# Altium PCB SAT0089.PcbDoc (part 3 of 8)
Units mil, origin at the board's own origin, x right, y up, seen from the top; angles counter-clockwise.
Board outline 4075 x 2715 mil, 6 copper layers (Top Layer, InternalPlane1, MidLayer1, Internal Plane 3, InternalPlane2, Bottom Layer), stack 67.4 mil thick; 538 components, 405 nets, 1716 pads, 1236 vias.
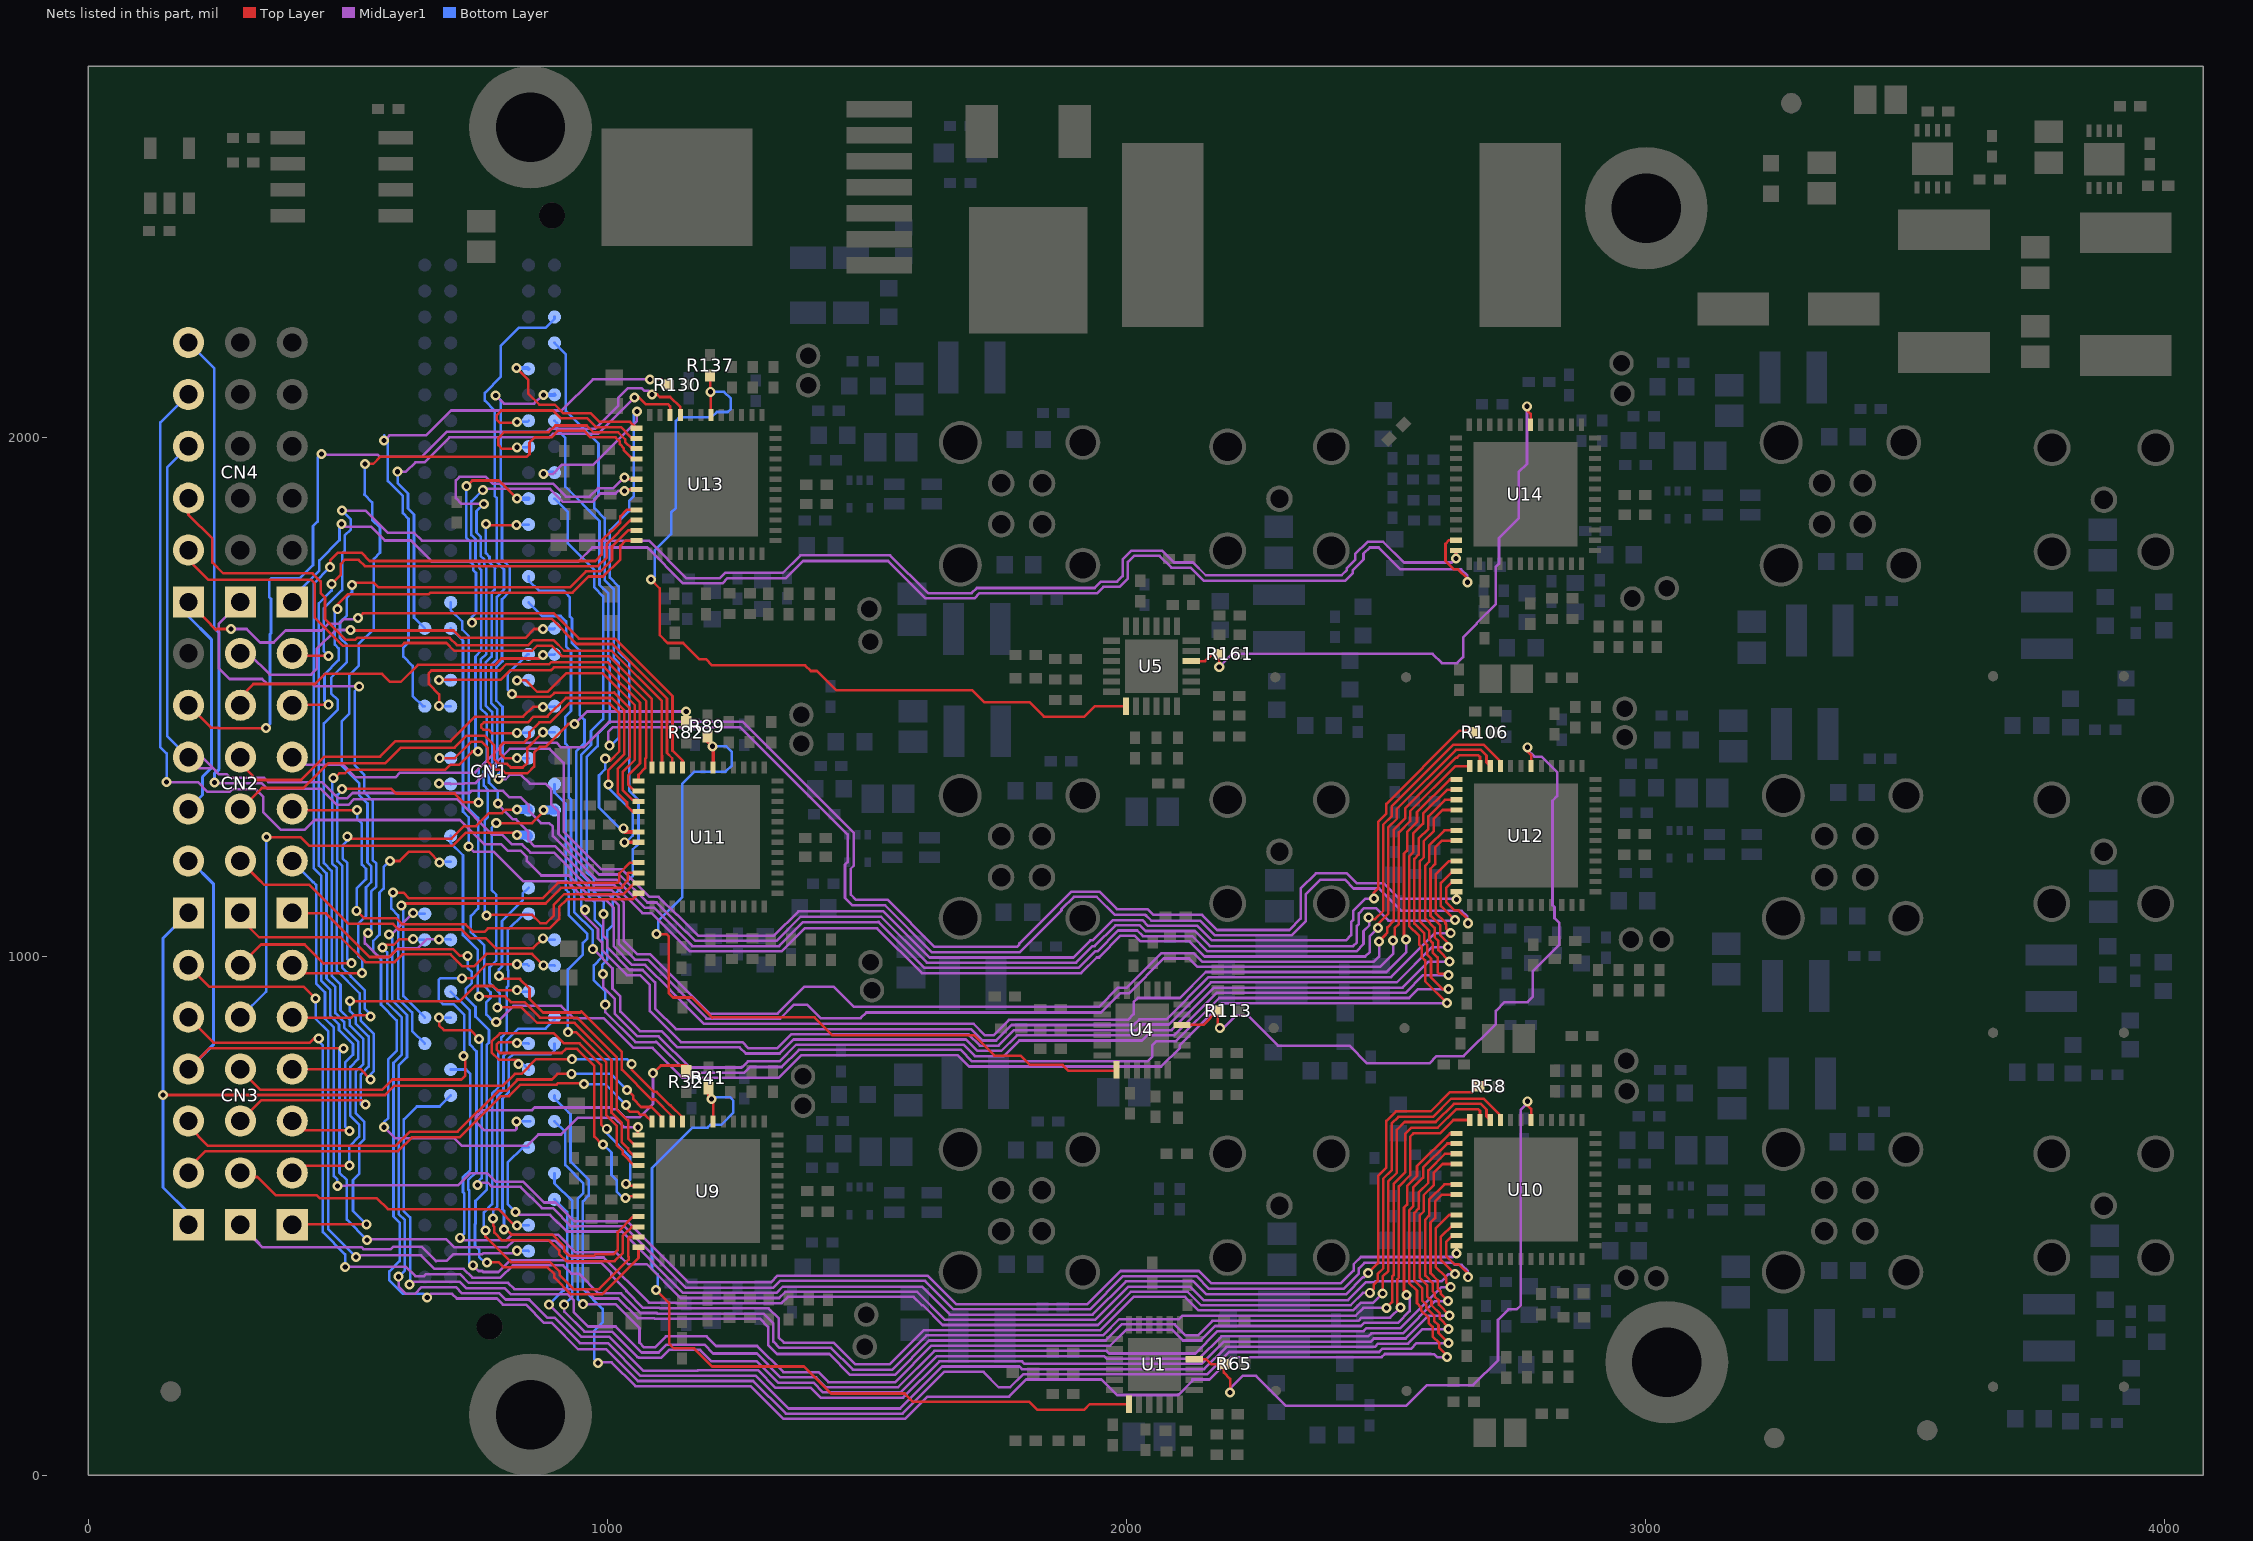
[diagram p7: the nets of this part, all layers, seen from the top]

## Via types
v1: diameter 19.29, hole 9.84, Top Layer to Bottom Layer, tented both sides, 1155 vias
v2: diameter 19.68, hole 7.87, Top Layer to Bottom Layer, tented both sides, 80 vias
v3: diameter 22, hole 10, Top Layer to Bottom Layer, tented both sides, 1 vias

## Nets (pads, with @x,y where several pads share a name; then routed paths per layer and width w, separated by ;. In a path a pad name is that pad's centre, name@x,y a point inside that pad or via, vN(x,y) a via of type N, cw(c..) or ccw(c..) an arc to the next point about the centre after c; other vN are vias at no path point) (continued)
BISTEN_CAM1: R41.1 U1.19 U9.6 | length 1636.1
  Top Layer w5: v1(1094,357) 1119,332 1119,254 1128,245 1167,245 1202,210 1379,210 1431,158 1573,158 1589,142 1813,142 1828,127 1919,127 1929.23,137.23 U1.19@2004.79,137.23 ; R41.1@1195,746 1195,731 v1(1201,725) 1203.84,722.16 U9.6@1203.84,681.86
  Bottom Layer w5: v1(1094,357) 1097,360 1097,388 1096,388 1086,398 1086,592 1164,670 1193,670 1198.5,675.5 1219.5,675.5 1243,699 1243,722 1236,729 1205,729 v1(1201,725)
BISTEN_CAM2: R65.1 U1.4 U10.6 | length 1287.3
  Top Layer w5: U1.4@2130.77,223.84 2154.16,223.84 2164,214 2187,214 2188,215 2188,198 2200,186 v1(2200,160) ; v1(2773,721) 2773,713 2779.84,706.16 U10.6@2779.84,684.86 U10.6@2780,685.02
  MidLayer1 w5: v1(2200,160) 2200,168 2224,192 2250,192 2308,134 2539,134 2579,174 2668,174 2716,222 2716,300 2736,320 2752,320 2760,328 2760,704.75 2773,717.75 v1(2773,721)
BISTEN_CAM3: R89.1 U4.19 U11.6 | length 1612.6
  Top Layer w5: v1(1095,1043) 1114,1043 1118,1039 1118,930 1127,921 1163,921 1202,882 1202.5,882.5 1399.5,882.5 1434,848 1707,848 1746,809 1796,809 1814,791 1877,791 1888,780 1979.76,780 U4.19@1981.34,781.57
  Top Layer w7: R89.1@1193,1424 1193,1415 v1(1203,1405) 1203.84,1404.16 U11.6@1203.84,1363.86
  Bottom Layer w5: v1(1095,1043) 1098,1046 1098,1068 1144,1114 1144,1332 1168,1356 1228,1356 1240,1368 1240,1394 1229,1405 v1(1203,1405)
BISTEN_CAM4: R113.1 U4.4 U12.6 | length 1417.2
  Top Layer w5: U4.4@2107.32,868.19 2148.35,868.19 2175.91,895.75 2175.91,866.09 v1(2180,862) ; v1(2773,1403) 2773,1395 2779.84,1388.16 U12.6@2779.84,1366.86 U12.6@2780,1367.02
  MidLayer1 w5: v1(2180,862) 2187,862 2212,887 2233,887 2292,828 2429.5,828 2463.5,794 2584,794 2598,808 2650,808 2712,870 2712,895 2729,912 2773,912 2783,922 2783,971 2834,1022 2834,1065 2825,1074 2825,1095 2821,1099 2821,1300 2830,1309 2830,1355 2800,1385 2786,1385 2773,1398 v1(2773,1403)
BISTEN_CAM5: R137.1 U5.19 U13.6 | length 1667.7
  Top Layer w5: v1(1084,1726) 1101,1709 1101,1619 1116,1604 1146,1604 1177,1573 1190,1573 1202,1561 1381,1561 1392,1550 1404,1550 1441,1513 1703,1513 1726,1490 1813,1490 1841,1462 1919,1462 1939.36,1482.36 U5.19@1999.06,1482.36 ; R137.1@1198,2119 1198,2089 v1(1199,2088) 1199,2044.23 U13.6@1199.84,2043.39
  Bottom Layer w5: v1(1084,1726) 1091,1733 1091,1782 1123,1814 1123,1855 1132,1864 1132,2032 1139,2039 1201,2039 1211,2049 1232,2049 1238,2055 1238,2075 1225,2088 v1(1199,2088)
BISTEN_CAM6: R161.1 U5.4 U14.6 | length 1159
  Top Layer w5: U5.4@2125.04,1568.98 2151.98,1568.98 2166,1583 2179,1583 2179,1565 2180,1564 2179,1563 v1(2179,1558) ; v1(2772,2060) 2772,2052 2778.84,2045.16 U14.6@2778.84,2024.39 ; U14.6@2778.84,2024.39 2779,2024.23 2779,2024.02 2778.84,2023.86 U14.6@2778.84,2024.39
  MidLayer1 w5: v1@2186,1558 v1(2179,1558) 2204,1583 2590,1583 2608,1565 2637,1565 2649,1577 2649,1615 2675,1641 2675,1642 2712,1679 2712,1751 2718,1757 2718,1806 2756,1844 2756,1933 2772,1949 v1(2772,2060)
CAM1_D0: CN2.1 U9.24 | length 1402.9
  Top Layer w5: CN2.1@393,1083 458,1083 542,999 579,999 587,1007 588,1007 595,1014 703,1014 716,1001 v1(731,1001) ; v1@762,410 v1(768,410) 768.5,410.5 791,410.5 800.5,401 885,401 898,388 898,381 930,349 990,349 1060.14,419.14 U9.24@1060.14,439.73
  Bottom Layer w5: v1(731,1001) 731,978 739,970 739,949 727,937 727,922 746,903 746,884 772,858 772,834 768,830 768,551 746,529 746,485 745,484 745,443 753,435 753,421 764,410 v1(768,410)
CAM1_D0_CAM1_VS: CN1.133 CN2.7 | length 685.2
  Top Layer w5: CN2.7@293,1083 293,1073 329,1037 486,1037 534,989 590,989 605,1004 698,1004 721,981 743,981 767,1005 855,1005 v1(877,983)
  Bottom Layer w5: v1(877,983) 897.43,983 CN1.133@898.27,982.17
CAM1_D1: CN1.95 U9.23 | length 1080.8
  Top Layer w5: v1(765,472) 765,460 814,411 890,411 908,393 908,386 935,359 984,359 1041,416 1041,421 1040,422 1040,457 1042.42,459.42 U9.23@1060.14,459.42
  Bottom Layer w5: v1@772,473 771,472 v1(765,472) 762,475 762,507 778,523 778,736 790,748 790,813 796,819 796,844 806,854 806,940 809,943 809,973 808,974 808,1051 839.17,1082.17 CN1.95@848.27,1082.17
CAM1_D2: CN1.131 U9.22 | length 845.6
  Top Layer w5: v1(780,495) 780,481.5 782.5,479 782.5,468 797.5,453 887.5,453 907,433.5 907,427 921,413 1014,413 1030,429 1030,462 1047.1,479.1 U9.22@1060.14,479.1
  Bottom Layer w5: v1(780,495) 780,510 788,518 788,731 800,743 800,808 806,814 806,838 829,861 881,861 898.27,878.27 CN1.131@898.27,882.17
CAM1_D3: CN1.130 U9.21 | length 790.9
  Top Layer w5: v1@798,481 v1@801,478 ; v1(801,474) v1@801,478 ; U9.21@1060.14,498.79 1049.79,498.79 1019.5,468.5 1020,468 1020,434 1012.5,426.5 977.5,426.5 974,423 926,423 917,432 917,441 894,464 815,464 v1@801,478
  Bottom Layer w5: v1(801,474) 801,510 798,513 798,726 810,738 810,803 819,812 891,812 898.27,819.27 CN1.130@898.27,832.17
CAM1_D4: CN1.90 U9.19 | length 592
  Top Layer w5: v1(826,833) 824,835 791,835 787,831 787,820 793,814 912,814 920,822 942,822 975,789 975,653 990,638 v1(992,638) ; v1(1035,535) 1038.16,538.16 U9.19@1060.14,538.16
  Bottom Layer w5: v1(826,833) 847.43,833 CN1.90@848.27,832.17 ; v1(992,638) 1008,622 1008,579 1018,569 1018,547 1030,535 v1(1035,535)
CAM1_D5: CN1.89 U9.18 | length 636.6
  Top Layer w5: v1(829,793) 829,801 791,801 777,815 777,836 793,852 897,852 916.5,832.5 946.5,832.5 988,791 988,676 996,668 v1(999,668) ; v1(1036,562) 1040.16,557.84 U9.18@1060.14,557.84
  Bottom Layer w5: v1(829,793) 837.43,793 CN1.89@848.27,782.17 ; v1(999,668) 999,659 1044,614 1044,570 v1(1036,562)
CAM1_D6: CN1.140 U9.16 | length 846.9
  Top Layer w5: v1(924,854) 940,854 998,796 998,694 1018,674 1018,637 1030,625 1030,619 1051.79,597.21 U9.16@1060.14,597.21
  Bottom Layer w5: CN1.140@898.27,1332.17 898.27,1315.73 920,1294 920,1129 925.5,1123.5 925.5,1079.5 961,1044 961,1034 953,1026 953,1004 924,975 v1(924,854)
CAM1_D7: CN1.139 U9.15 | length 978.3
  Top Layer w5: v1(786,1257) 855,1257 879,1281 878,1281 v1(877,1282) ; v1(788,902) 835,902 865,872 937,872 1008,801 1008,699 1028,679 1028,642 1040,630 1040,627 1050.1,616.9 U9.15@1060.14,616.9
  Bottom Layer w5: v1(786,1257) 777,1248 777,1128 786,1119 786,992 773,979 773,949 793,929 793,907 v1(788,902)
  Bottom Layer w17.72: v1(877,1282) 898.1,1282 CN1.139@898.27,1282.17
CAM1_D8: CN1.58 U9.14 | length 840.9
  Top Layer w5: v1(753,923) 769,923 770,922 771,923 803,923 814,912 840,912 870,882 942,882 1018,806 1018,705 1039,684 1040,684 1040,649 1052.42,636.58 U9.14@1060.14,636.58
  Bottom Layer w5: CN1.58@698.27,1232.17 698.27,1218.73 722,1195 722,1041 750,1013 750,926 v1(753,923) v1@755,921
CAM1_D9: CN1.57 U9.13 | length 1246.1
  Top Layer w5: v1(581,1184) 600,1184 618,1202 656,1202 v1(677,1181) ; v1(1059,671) 1059,657.41 U9.13@1060.14,656.27
  MidLayer1 w5: v1(570,671) 591,650 705,650 720,635 845,635 867,657 911,657 943,689 1014,689 1032,671 v1(1059,671)
  Bottom Layer w5: v1@578,670 577,671 v1(570,671) 570,681 578,689 578,802 594,818 594,877 564,907 564,995 549,1010 549,1030 561,1042 561,1123 569,1131 569,1172 v1(581,1184) ; v1(677,1181) 678.17,1182.17 CN1.57@698.27,1182.17
CAM1_D10: CN3.14 U9.12 | length 1010.5
  Top Layer w5: CN3.14@193,582 CN3.14@193,583 193,592 226,625 597,625 623.5,651.5 715.5,651.5 795,731 811,731 833,753 902,753 905,756 953,756 v1(955,754) ; v1(1036,714) 1032,714 1032,712 1043,701 1058,701 1064,695 1072.59,695 U9.12@1085.73,681.86
  Bottom Layer w5: v1(955,754) 996,754 v1(1036,714)
CAM1_D11: CN3.15 U9.11 | length 1043.1
  Top Layer w5: CN3.15@193,683 193,673 231,635 592,635 619.5,662.5 711.5,662.5 790,741 806,741 826,761 826,763 893,763 904,774 v1(931,774) ; v1(1038,743) 1050,731 1050,725 1065,710 1085,710 1105.42,689.58 U9.11@1105.42,681.86
  Bottom Layer w5: v1(931,774) 1007,774 v1(1038,743)
CAM1_HS: CN1.96 U9.10 | length 687.8
  Top Layer w5: U9.10@1125.1,681.86 1125.1,691.9 1092.5,724.5 1085.5,724.5 1028,782 1028,816 950,894 948,892 876,892 850,918 850,938 832,956 832,957 796,957 v1@793,960 ; v1@793,960 v1(791,962) 791,960 v1@793,960
  Bottom Layer w5: v1(791,962) 791,975 797,981 797,1068 837,1108 837,1120.9 CN1.96@848.27,1132.17
CAM1_PCLK: CN1.87 R32.1 | length 644.1
  Top Layer w5: v1(1088,775) 1103,790 1152,790 R32.1@1152,779
  MidLayer1 w5: v1(825,682) 825,668 822,665 763,665 747,681 747,691 760,704 855,704 860,709 1006,709 1009,706 1018,706 1034,690 1062,690 1088,716 v1(1088,775)
  Bottom Layer w5: v1(825,682) 825.17,682.17 CN1.87@848.27,682.17 CN1.87@851.83,682.17
CAM1_VS: CN2.13 CN3.13 U9.9 | length 1737.1
  Top Layer w5: v1(144,733) 572,733 590,751 799,751 822,774 835,774 863,802 v1(932,802) ; CN3.13@192,483 CN3.13@193,483 CN3.13@193,482 ; v1(1047,793) 1047,782 1090,739 1095,739 1121,713 1122,713 1144.79,690.21 U9.9@1144.79,681.86
  Bottom Layer w5: v1(932,802) 1038,802 v1(1047,793)
  Bottom Layer w6: CN3.13@193,482 CN3.13@193,483 193,506 144,555 v1(144,733) 144,1035 CN2.13@192,1083 ; CN2.13@192,1083 CN2.13@193,1084 193,1083 CN2.13@192,1083
CAM2_D0: CN2.2 U10.24 | length 3084
  Top Layer w5: v1(2636,428) 2636.14,428.14 U10.24@2636.14,442.73
  MidLayer1 w5: v1(480,558) 497,558 498,559 712,559 735,582 769,582 785,566 838,566 878,526 900,526 936,490 1038,490 1156,372 1315,372 1328,385 1617,385 1672,330 1925,330 1989,394 2140,394 2164,370 2413,370 2438,395 2438,407 2452,421 2629,421 v1(2636,428)
  Bottom Layer w5: v1(480,558) 480,570 473,577 473,863 456,880 456,931 439,948 439,1138 434,1143 ; 434,1143 433,1143 393,1183 CN2.2@393,1184 434,1143
CAM2_D0_CAM2_VS: CN1.134 CN2.8 | length 738.9
  Top Layer w5: v1(876,1035) 857,1016 785,1016 766,1035 736,1035 719,1052 598,1052 587,1063 501,1063 426,1138 339,1138 331.5,1145.5 ; 331.5,1145.5 330.5,1145.5 293,1183 CN2.8@293,1184 331.5,1145.5
  Bottom Layer w5: v1(876,1035) 878.83,1032.17 CN1.134@898.27,1032.17
CAM2_D1: CN1.51 U10.23 | length 2630.6
  Top Layer w5: v1(676,882) 676,867 685,858 736,858 v1(753,841) ; U10.23@2636.14,462.42 2628.42,462.42 2616,450 2616,423 2632,407 2640,407 2658,389 v1(2658,382)
  MidLayer1 w5: v1(750,560) 754,564 770,564 778,556 833,556 874,515 895,515 930,480 1033,480 1151,362 1320,362 1333,375 1612,375 1667,320 1930,320 1994,384 2135,384 2159.5,359.5 2418.5,359.5 2448,389 2448,399 2458.5,409.5 2629.5,409.5 2633,406 2646,406 2658,394 v1(2658,382)
  Bottom Layer w5: v1(676,882) 698.1,882 CN1.51@698.27,882.17 ; v1(750,560) 750,566 751,566 758,573 758,836 v1(753,841)
CAM2_D2: CN1.49 U10.22 | length 2549
  Top Layer w5: v1(2633,388) 2606,415 2606,460 2628.1,482.1 U10.22@2636.14,482.1
  MidLayer1 w5: v1(716,458) 721,453 805,453 816,464 905,464 939,430 1017,430 1040,407 1076,407 1141,342 1331,342 1343,354 1597,354 1651,300 1940,300 2004,364 2123,364 2149,338 2427,338 2461,372 2478,372 2480,374 2607,374 2621,388 v1(2633,388)
  Bottom Layer w5: CN1.49@698.27,782.17 727.83,782.17 736,774 736,589 722,575 722,546 724,544 724,466 v1(716,458)
CAM2_D3: CN1.48 U10.21 | length 2810.8
  Top Layer w5: v1(2625,363) 2616,372 2616,380 2615,381 2615,383 2596,402 2596,476 2621.79,501.79 U10.21@2636.14,501.79
  MidLayer1 w5: v1(619,368) 624,373 716,373 728,361 802,361 814,349 924,349 935,338 935,315 963,287 1016,287 1066,237 1099,237 1114,252 1187,252 1204,235 1288,235 1334,189 1402,189 1421,170 1560,170 1630,240 1962,240 1967,235 2133,235 2176,278 2457,278 2463,284 2528,284 2607,363 v1(2625,363)
  Bottom Layer w5: v1(619,368) 620,369 620,497 608,509 608,686 633,711 677.1,711 CN1.48@698.27,732.17
CAM2_D4: CN1.125 U10.19 | length 2400.3
  Top Layer w5: v1(2620,336) 2605.5,350.5 2605.5,354.5 2600,360 2600,376 2586,390 2586,487 2595,496 2595,528 2608.16,541.16 U10.19@2636.14,541.16
  MidLayer1 w5: v1(917,329) 917,316 956,277 1009,277 1058,228 1060,228 1061,227 1104,227 1119,242 1179,242 1201,220 1288,220 1329,179 1397,179 1416,160 1565,160 1635,230 1957,230 1962,225 2140,225 2183,268 2466,268 2472,274 2533,274 2595,336 v1(2620,336)
  Bottom Layer w5: CN1.125@898.27,582.17 898.27,562.73 932.5,528.5 932.5,344.5 v1(917,329)
CAM2_D5: CN1.124 U10.18 | length 2418.5
  Top Layer w5: v1(2623,308) 2602,329 2602,337 2594,345 2594,351 2590,355 2590,371 2576,385 2576,493 2583.5,500.5 2583.5,531.5 2612.84,560.84 U10.18@2636.14,560.84
  MidLayer1 w5: v1(888,329) 950,267 1004,267 1069,202 1174,202 1175,203 1290,203 1324,169 1392,169 1411,150 1570,150 1640,220 1799,220 1804,215 2145,215 2188,258 2471,258 2477,264 2538,264 2582,308 v1(2623,308)
  Bottom Layer w5: v1(888,329) 915,356 916,356 922.5,362.5 922.5,507.93 CN1.124@898.27,532.17
CAM2_D6: CN1.15 U10.16 | length 3382.4
  Top Layer w5: v1(2621,282) 2621,285 2604,302 2604,312 2588,328 2588,336 2580,344 2580,366 2565,381 2565,501 2573,509 2573,540 2592,559 2592,583 2609.21,600.21 U10.16@2636.14,600.21
  MidLayer1 w5: v1(579,1042) 584,1042 v1(626,1084) ; v1(598,383) 598,364 612,350 629,350 642,363 708,363 720,351 792,351 804,339 850,339 850,338 884,304 898,304 947,255 1001,255 1064,192 1286,192 1349,129 1564,129 1645,210 1794,210 1799,205 2150,205 2193,248 2479,248 2485,254 2543,254 2571,282 v1(2621,282)
  Bottom Layer w5: v1(579,1042) 586,1035 586,915 614,887 614,806 598,790 598,504 610,492 610,395 v1(598,383) ; v1(626,1084) 627.83,1082.17 CN1.15@648.27,1082.17
CAM2_D7: CN1.14 U10.15 | length 3439.2
  Top Layer w5: v1(567,1017) 572.5,1022.5 588.5,1022.5 599,1033 625,1033 v1(626,1034) ; v1(2621,255) 2601.5,274.5 2601.5,289.5 2593,298 2593,308 2578,323 2578,329 2570,337 2570,361 2555,376 2555,506 2563,514 2563,545 2582,564 2582,588 2613.9,619.9 U10.15@2636.14,619.9
  MidLayer1 w5: v1(653,343) 660,350 701,350 710,341 787,341 799,329 843,329 878,294 893,294 944,243 998,243 1059,182 1281,182 1344,119 1569,119 1650,200 1725,200 1725,199 1754,170 1776,170 1801,195 2155,195 2198,238 2487,238 2493,244 2548,244 2559,255 v1(2621,255)
  Bottom Layer w5: v1(567,1017) 576,1008 576,910 604,882 604,811 588,795 588,499 600,487 600,413 580,393 580,376 606,350 646,350 v1(653,343) ; v1(626,1034) 627.83,1032.17 CN1.14@648.27,1032.17
CAM2_D8: CN1.128 U10.14 | length 2824.9
  Top Layer w5: v1(2618,228) 2618,231 2603,246 2603,255 2590,268 2590,286 2583,293 2583,303 2568,318 2568,324 2560,332 2560,356 2545,371 2545,511 2553,519 2553,554 2552.5,554.5 2572,574 2572,593 2618.58,639.58 U10.14@2636.14,639.58
  MidLayer1 w5: v1(982,217) 983,218 1008,218 1054,172 1276,172 1339,109 1574,109 1617,152 1774,152 1807,185 1952,185 1982,155 2099,155 2100,156 2101,156 2127,182 2127,185 2160,185 2203,228 2492,228 2498,234 2587,234 2587.5,233.5 2593.5,233.5 2599,228 v1(2618,228)
  Bottom Layer w5: CN1.128@898.27,732.17 898.27,726.73 929,696 929,605 964,570 964,539 953,528 953,359 991,321 991,295 975,279 975,224 v1(982,217)
CAM2_D9: CN1.127 U10.13 | length 2552
  Top Layer w5: v1(2540,348) 2540,356 2535,356 2535,516 2541,522 2541,558 2560,577 2560,596 2623.27,659.27 U10.13@2636.14,659.27
  MidLayer1 w5: v1@948,332 950,330 v1(953,330) 1016,330 1062,284 1062,256 1071,247 1092,247 1113,268 1191,268 1209.5,249.5 1288.5,249.5 1339,199 1407,199 1426,180 1555,180 1625,250 1969,250 2000,281 2088,281 2109,260 2143,260 2171,288 2452,288 2458,294 2523,294 2546,317 2546,342 v1(2540,348)
  Bottom Layer w5: CN1.127@898.27,682.17 919,661.43 919,598 954,563 954,544 943,533 943,340 v1(953,330)
CAM2_D10: CN3.17 U10.12 | length 3420.9
  Top Layer w5: CN3.17@193,883 193,882 241,834 427,834 435,842 v1(444,842) ; v1(2528,324) 2522,330 2522,378 2525,381 2525,557 2547,579 2547,653 2553,659 2604.14,659 2630,684.86 U10.12@2661.73,684.86
  MidLayer1 w5: v1(495,402) 612,402 630,384 647,384 651,388 716,388 733,371 809,371 821,359 957,359 975,341 1021,341 1059,303 1090,303 1091,302 1294,302 1310,286 1310,251 1327,234 1428,234 1468,194 1554,194 1620,260 1960,260 1991,291 2094,291 2094,290 2114,270 2138,270 2166,298 2447,298 2453,304 2508,304 v1(2528,324)
  Bottom Layer w5: v1(444,842) 444,836 452,828 452,469 495,426 v1(495,402)
CAM2_D11: CN3.18 U10.11 | length 3503.4
  Top Layer w5: CN3.18@193,983 193,982 233,942 415,942 v1(438,919) ; v1(2501,323) 2512,334 2512,383 2515,386 2515,562 2537,584 2537,658 2549,670 2600,670 2636,706 2678,706 2681.42,702.58 U10.11@2681.42,684.86
  MidLayer1 w5: v1(516,421) 519,424 641,424 667,398 723,398 740,381 794,381 818,405 915,405 931,389 945,389 983,351 1027,351 1027,350 1064,313 1095,313 1096,312 1301,312 1320,293 1320,258 1332,246 1431,246 1473,204 1549,204 1615,270 1955,270 1986,301 2101,301 2108,308 2442,308 2457,323 v1(2501,323)
  Bottom Layer w5: v1(438,919) 438,880 462,856 462,475 v1(516,421)
CAM2_HS: CN1.52 U10.10 | length 3066.3
  Top Layer w5: v1(2494,351) 2494,383 2505,394 2505,567 2521,583 2521,666 2536,681 2596,681 2631,716 2683,716 2694,705 2694,691.96 U10.10@2701.1,684.86
  MidLayer1 w5: v1(741,405) 752,394 759,394 761,392 790,392 813,415 920,415 925,410 988,410 1008,390 1008,385 1037,356 1037,355 1069,323 1100,323 1101,322 1311,322 1330,303 1330,266 1340,256 1436,256 1478,214 1544,214 1610,280 1950,280 2014,344 2113,344 2139,318 2437,318 2452,333 2476,333 v1(2494,351)
  Bottom Layer w5: CN1.52@698.27,932.17 735,895.43 735,830 748,817 748,585 732,569 732,551 734,549 734,409 741,402 v1(741,405)
CAM2_PCLK: CN1.86 R58.1 | length 2454.6
  Top Layer w5: v1(2466,390) 2485,409 2485,577 2501,593 2501,683 2519.5,701.5 2586.5,701.5 2623.5,738.5 2666.5,738.5 R58.1@2678,750
  MidLayer1 w5: v1(823,508) 829,502 890,502 922,470 1028,470 1146,352 1326,352 1338,364 1606,364 1660,310 1935,310 1999,374 2129,374 2154,349 2423,349 2456,382 2458,382 v1(2466,390)
  Bottom Layer w5: v1(823,508) 808,523 808,603 837.17,632.17 CN1.86@848.27,632.17
CAM2_VS: CN2.14 CN3.16 U10.9 | length 3871
  Top Layer w5: 226,815 193,782 CN3.16@193,783 233,823 v1(492,823) ; v1(2469,352) 2477,360 2477,368 2484,375 2484,388 2495,399 2495,572 2511,588 2511,678 2524,691 2591,691 2626,726 2688,726 2720.79,693.21 U10.9@2720.79,684.86
  MidLayer1 w5: v1(537,454) 538,455 690,455 705,440 807,440 819,452 900,452 932,420 993,420 1080,333 1132,333 1133,332 1336,332 1348,344 1590,344 1606,328 1608,328 1646,290 1945,290 2009,354 2118,354 2144,328 2432,328 2456,352 v1(2469,352)
  Bottom Layer w5: v1(492,823) 487,823 486,824 484,822 484,583 498,569 498,493 v1(537,454)
  Bottom Layer w6: CN2.14@193,1183 198,1183 241,1140 241,830 CN3.16@194,783 ; CN3.16@194,783 CN3.16@193,783 193,782 CN3.16@194,783
CAM3_D0: CN2.3 U11.24 | length 937.6
  Top Layer w5: CN2.3@393,1283 394,1282 v1(518,1282) ; v1(517,1088) 531,1074 593,1074 605,1062 727,1062 741,1048 764,1048 770,1054 889,1054 907,1072 907,1095 922,1110 1048.41,1110 U11.24@1060.14,1121.73
  Bottom Layer w5: v1(517,1088) 517,1131 535,1149 535,1169 527,1177 527,1256 518,1265 v1(518,1282)
CAM3_D0_CAM3_VS: CN1.142 CN2.9 | length 750.4
  Top Layer w5: CN2.9@293,1283 334.5,1324.5 414.5,1324.5 462,1372 572,1372 602.5,1402.5 705.5,1402.5 728,1425 764,1425 782,1407 782,1380 791,1371 807,1371 814,1364 837,1364 846,1373 846,1402 v1(876,1432)
  Bottom Layer w5: v1(876,1432) 898.1,1432 CN1.142@898.27,1432.17
CAM3_D1: CN1.110 U11.23 | length 1240.7
  Top Layer w5: v1(766,1833) 765,1833 763,1831 v1(825,1831) ; v1@767,1072 v1(767,1079) 768,1080 855,1080 871,1064 882,1064 897,1079 897,1100 917,1120 1031,1120 1052.42,1141.42 U11.23@1060.14,1141.42
  Bottom Layer w5: v1(766,1833) 766,1777 773,1770 773,1759 784,1748 783,1747 783,1707 777,1701 777,1578 766,1567 766,1483 778,1471 778,1373 762,1357 762,1329 770,1321 770,1269 764,1263 764,1073 767,1076 v1(767,1079) ; v1(825,1831) 826.17,1832.17 CN1.110@848.27,1832.17
CAM3_D2: CN1.11 U11.22 | length 727.8
  Top Layer w5: v1(603,1098) 607,1102 881,1102 911,1132 1028,1132 1030,1134 1030,1137 1039,1146 1039,1160 1040.1,1161.1 U11.22@1060.14,1161.1
  Bottom Layer w5: v1(603,1098) 607,1094 607,923.43 CN1.11@648.27,882.17
CAM3_D3: CN1.10 U11.21 | length 845.7
  Top Layer w5: v1(587,1123) 607,1123 618,1112 875,1112 905,1142 1020,1142 1023,1145 1023,1160 1043.79,1180.79 U11.21@1060.14,1180.79
  Bottom Layer w5: v1(587,1123) 587,1126 584,1129 584,1092 597,1079 597,919 624,892 624,856.43 CN1.10@648.27,832.17
CAM3_D4: CN1.102 U11.19 | length 731.7
  Top Layer w5: v1(826,1431) 825,1430 778,1430 771,1437 761,1437 757,1441 757,1446 762,1451 847,1451 858,1462 885,1462 885,1463 920,1498 1009,1498 1033,1474 1033,1390 1002,1359 v1(1002,1331)
  Top Layer w7: v1(1033,1220) 1033.84,1220 1034,1220.16 U11.19@1060.14,1220.16
  Bottom Layer w5: v1(826,1431) 847.1,1431 CN1.102@848.27,1432.17 ; v1(1002,1331) 1002,1325 1049,1278 1049,1233 1036,1220 v1(1033,1220)
CAM3_D5: CN1.101 U11.18 | length 660.5
  Top Layer w5: v1(826,1382) 802,1382 794,1390 794,1406 800,1412 839,1412 850,1423 850,1432 869,1451 890,1451 926.5,1487.5 1004.5,1487.5 1023,1469 1023,1395 1005,1377 1001,1381 v1(996,1381) v1@992,1381
  Top Layer w7: v1(1031,1247) 1031,1242.84 1034,1239.84 U11.18@1060.14,1239.84
  Bottom Layer w5: v1(826,1382) 848.1,1382 CN1.101@848.27,1382.17 ; v1(996,1381) 996,1361 984,1349 984,1287 1024,1247 v1(1031,1247)
CAM3_D6: CN1.105 U11.16 | length 575.6
  Top Layer w5: v1(816,1506) 822,1500 890,1500 898,1508 1012,1508 1013,1509 1043,1479 1043,1384 1020,1361 1020,1315 1038,1297 1038,1290 1048.79,1279.21 U11.16@1060.14,1279.21
  Bottom Layer w5: v1(816,1506) 808,1514 808,1544 846.17,1582.17 CN1.105@848.27,1582.17
CAM3_D7: CN1.104 U11.15 | length 511.5
  Top Layer w5: v1(826,1532) 843,1532 865,1510 885,1510 921,1546 991,1546 1053,1484 1053,1379 1030,1356 1030,1320 1048,1302 1057.04,1302 U11.15@1060.14,1298.9
  Bottom Layer w5: v1(826,1532) 848.1,1532 CN1.104@848.27,1532.17
CAM3_D8: CN1.64 U11.14 | length 640.8
  Top Layer w5: v1(676,1533) 794.5,1533 813,1551.5 892,1551.5 892,1552 897,1557 995,1557 1063,1489 1063,1372 1040,1349 1040,1331 1052.42,1318.58 U11.14@1060.14,1318.58
  Bottom Layer w5: v1(676,1533) 676.83,1532.17 CN1.64@698.27,1532.17
CAM3_D9: CN1.63 U11.13 | length 712.5
  Top Layer w5: v1(676,1483) 676,1505 656,1525 656,1546 661,1551 793,1551 805,1563 888,1563 892,1567 1000,1567 1075,1492 1075,1383 1073,1381 1073,1362.86 1060.14,1350 U11.13@1060.14,1338.27
  Bottom Layer w5: v1(676,1483) 676.83,1482.17 CN1.63@698.27,1482.17
CAM3_D10: CN4.14 U11.12 | length 1206.1
  Top Layer w5: CN4.14@193,1783 193,1764 231,1726 429,1726 436.5,1718.5 436.5,1652.5 490,1599 604,1599 609,1604 690,1604 705,1589 855,1589 865,1599 892,1599 912.5,1578.5 1003.5,1578.5 1085.73,1496.27 U11.12@1085.73,1363.86
CAM3_D11: CN4.15 U11.11 | length 1295.9
  Top Layer w5: CN4.15@193,1883 193,1851 239,1805 239,1759 260,1738 432,1738 447.5,1722.5 447.5,1700.5 456,1692 456,1650.5 496.5,1610 514,1610 518,1614 696,1614 710,1600 848,1600 857,1609 897,1609 917,1589 1008,1589 1105,1492 1105,1387 1105.42,1386.58 U11.11@1105.42,1363.86
CAM3_HS: CN1.111 U11.10 | length 993.4
  Top Layer w5: v1(729,1906) 740,1917 791,1917 v1(826,1882) ; v1(739,1643) 747,1651 892,1651 941,1602 1010,1602 1115,1497 1115,1392 1125.1,1381.9 U11.10@1125.1,1363.86
  Bottom Layer w5: v1(729,1906) 728,1905 728,1807 736,1799 736,1760 742,1754 742,1744 747,1739 747,1662 739,1654 v1(739,1643)
  Bottom Layer w8: v1(826,1882) 848.1,1882 CN1.111@848.27,1882.17
CAM3_PCLK: CN1.61 R82.1 | length 645.2
  Top Layer w5: v1(677,1382) 707,1382 707,1383 738,1414 758,1414 770,1402 770,1375 785,1360 797,1360 804,1353 846,1353 859,1366 859,1393 870,1404 881,1404 925,1448 v1(937,1448) ; v1@1146,1472 v1(1152,1472) 1152,1452 R82.1@1150,1454
  MidLayer1 w5: v1(937,1448) 961,1472 v1(1152,1472)
  Bottom Layer w5: v1(677,1382) 698.1,1382 CN1.61@698.27,1382.17
CAM3_VS: CN2.15 CN4.13 U11.9 | length 1643.4
  Top Layer w5: CN4.13@193,1683 236,1640 236,1639 246,1629 248,1631 v1(275,1631) ; v1(520,1652) 529,1661 897,1661 945.5,1612.5 1014.5,1612.5 1125.5,1501.5 1125.5,1396.5 1144.79,1377.21 U11.9@1144.79,1363.86
  MidLayer1 w5: v1(275,1631) 305,1631 331,1605 357,1605 380,1628 449,1628 462,1641 483.5,1641 492,1649.5 v1@517.5,1649.5 ; v1@517.5,1649.5 v1(520,1652) 520,1649.5 v1@517.5,1649.5
  Bottom Layer w6: CN2.15@193,1283 CN2.15@193,1284 220,1311 220,1346 237,1363 237,1611 193,1655 CN4.13@193,1683
CAM4_D0: CN2.4 U12.24 | length 2762.3
  Top Layer w5: v1(2636,1110) 2636.14,1110.14 U12.24@2636.14,1124.73
  MidLayer1 w5: CN2.4@393,1383 406.5,1369.5 490.5,1369.5 515,1345 592,1345 601,1354 745,1354 803,1412 902,1412 911,1403 954,1403 1003,1452 1261,1452 1475,1238 1475,1175 1469,1169 1469,1119 1478.5,1109.5 1539.5,1109.5 1630.5,1018.5 1789.5,1018.5 1794,1023 1794,1025 1894,1125 1948,1125 1982,1091 2041,1091 2052,1080 2146,1080 2175,1051 2314,1051 2336,1073 2336,1131 2365,1160 2425,1160 2444,1141 2496,1141 2526,1111 v1@2633,1111 ; v1@2633,1111 2634,1110 v1(2636,1110) 2635,1111 v1@2633,1111
CAM4_D0_CAM4_VS: CN1.143 CN2.10 | length 688.4
  Top Layer w5: CN2.10@293,1383 293,1372 325,1340 410,1340 455,1385 562,1385 592,1415 698,1415 745,1462 838,1462 857,1481 v1(876,1481)
  Bottom Layer w5: v1(876,1481) 897.1,1481 CN1.143@898.27,1482.17
CAM4_D1: CN1.157 U12.23 | length 3097.4
  Top Layer w5: U12.23@2636.14,1144.42 2628.42,1144.42 2616,1132 2616,1105 2632,1089 2640,1089 2658,1071 v1(2658,1064)
  MidLayer1 w5: v1@1005,1406 v1(1004.5,1406) 1002,1408.5 1002,1433 1011,1442 1256,1442 1463,1235 1463,1182 1458,1177 1458,1113 1472.5,1098.5 1535.5,1098.5 1626,1008 1794,1008 1875,1089 1875,1091 1899,1115 1943,1115 1978,1080 2036,1080 2037,1079 2038,1079 2048,1069 2142,1069 2170,1041 2319,1041 2346,1068 2346,1120 2374,1148 2421,1148 2438,1131 2487,1131 2530,1088 2646,1088 2657,1077 2657,1065 v1(2658,1064)
  Bottom Layer w5: CN1.157@898.27,2182.17 920.22,2160.22 920.22,2050.78 983,1988 983,1889 975,1881 975,1864 995,1844 995,1725 1012,1708 1012,1576 1022,1566 1022,1421 1007,1406 v1(1004.5,1406)
CAM4_D2: CN1.155 U12.22 | length 3217.4
  Top Layer w5: v1(2633,1070) 2606,1097 2606,1142 2628.1,1164.1 U12.22@2636.14,1164.1
  MidLayer1 w5: v1(785,2081) 801,2065 859,2065 876,2082 v1(877,2082) ; v1(790,1342) 804,1342 812,1350 834,1350 851,1333 881,1333 892,1322 892,1293 906,1279 906,1236 984,1158 1023,1158 1077,1104 1095,1104 1151,1048 1152,1048 1170,1030 1326,1030 1372.5,1076.5 1527.5,1076.5 1616,988 1903,988 1935,1020 1939,1020 1979,1060 2026,1060 2037,1049 2132,1049 2161,1020 2437,1020 2444,1027 2444,1059 2448,1063 2448,1083 2458,1093 2481,1093 2505,1069 v1@2632,1069 ; v1@2632,1069 v1(2633,1070) 2634,1069 v1@2632,1069
  Bottom Layer w5: v1(785,2081) 795,2071 795,1909 797,1907 797,1765 812,1750 812,1703 797,1688 797,1570 798,1569 786,1557 786,1493 798,1481 798,1360 790,1352 v1(790,1342)
  Bottom Layer w8: v1(877,2082) 898.1,2082 CN1.155@898.27,2082.17
CAM4_D3: CN1.154 U12.21 | length 3086.6
  Top Layer w5: v1(2625,1045) 2616,1054 2616,1062 2615,1063 2615,1065 2596,1084 2596,1158 2621.79,1183.79 U12.21@2636.14,1183.79
  MidLayer1 w5: v1(993,1082) 992,1081 992,1040 1000,1032 1000,1017 1043,974 1068,974 1092,950 1092,900 1132,860 1701,860 1723,838 1749,838 1779,868 2014,868 2025,879 2077,879 2158,960 2510,960 2595,1045 v1(2625,1045)
  Bottom Layer w5: CN1.154@898.27,2032.17 903,2027.43 903,2015 919,1999 919,1905 985,1839 985,1716 1002,1699 1002,1571 1005,1568 1005,1450.5 1003,1450.5 981.25,1428.75 981.25,1405.25 960,1384 960,1163 974,1149 974,1125 993,1106 v1(993,1082)
CAM4_D4: CN1.108 U12.19 | length 2920.3
  Top Layer w5: v1(2620,1018) 2620,1025.5 2605,1040.5 2605,1060 2587,1078 2586,1078 2586,1169 2595,1178 2595,1210 2608.16,1223.16 U12.19@2636.14,1223.16
  MidLayer1 w5: v1(957,1090) 956,1089 952,1089 952,1083 982,1053 982,1035 990,1027 990,1012 1038,964 1063,964 1082,945 1082,895 1142,835 1260,835 1272,823 1327,823 1354,850 1696,850 1718,828 1754,828 1784,858 2020,858 2031,869 2082,869 2163,950 2521,950 2589,1018 v1(2620,1018)
  Bottom Layer w5: CN1.108@848.27,1732.17 848.27,1724.73 868,1705 916,1705 919,1702 919,1701 928,1692 928,1655 932,1651 932,1604 946.5,1589.5 946.5,1465.5 956,1456 956,1411 940,1395 940,1144.5 949.5,1135 949.5,1097.5 v1(957,1090)
CAM4_D5: CN1.107 U12.18 | length 2925.9
  Top Layer w5: v1(2623,990) 2601,1012 2601,1030 2594,1037 2594,1055 2576,1073 2576,1175 2583.5,1182.5 2583.5,1213.5 2612.84,1242.84 U12.18@2636.14,1242.84
  MidLayer1 w5: v1(972,1014) 973,1014 1010,977 1010,938 1025,923 1025,894 1063,856 1104,856 1135,825 1255,825 1267,813 1332,813 1359,840 1691,840 1713,818 1759,818 1789,848 2025,848 2035,858 2087,858 2169,940 2532,940 2582,990 v1(2623,990)
  Bottom Layer w5: CN1.107@848.27,1682.17 874.43,1656 910,1656 920.5,1645.5 920.5,1597.5 930,1588 930,1473 919,1462 919,1410 926,1403 926,1306 930,1302 930,1134 936,1128 936,1086 972,1050 v1(972,1014)
CAM4_D6: CN1.152 U12.16 | length 3644.6
  Top Layer w5: v1(2621,964) 2618,967 2602,967 2599.75,969.25 2599.75,998.25 2590.25,1007.75 2590.25,1026.25 2584,1032.5 2584,1049 2565,1068 2565,1183 2573,1191 2573,1222 2592,1241 2592,1265 2609.21,1282.21 U12.16@2636.14,1282.21
  MidLayer1 w5: v1(877,1930) 878,1929 894,1929 912,1947 972,1947 1057,2032 v1(1057,2050) ; v1(992,966) 992,941 1014.5,918.5 1014.5,889.5 1058,846 1099,846 1159,786 1258,786 1259,787 1260,787 1271,798 1332,798 1364,830 1686,830 1708,808 1764,808 1794,838 2030,838 2040,848 2092,848 2174,930 2538,930 2572,964 v1(2621,964)
  Bottom Layer w5: v1(992,966) 990,968 990,984 1000,994 1000,1050 1010.5,1060.5 1010.5,1116.5 1049,1155 1049,1206 1060,1217 1060,1301.5 1042.5,1319 1042.5,1566.5 1022,1587 1022,1713 1005,1730 1005,1821 1042,1858 1042,1878 1051,1887 1051,2044 v1(1057,2050)
  Bottom Layer w8: v1(877,1930) 879.17,1932.17 CN1.152@898.27,1932.17
CAM4_D7: CN1.151 U12.15 | length 3295.4
  Top Layer w5: v1(2621,937) 2609.5,937 2587,959.5 2587,996 2579.5,1003.5 2579.5,1022.5 2574,1028 2574,1044.5 2555,1063.5 2555,1188 2563,1196 2563,1227 2582,1246 2582,1270 2613.9,1301.9 U12.15@2636.14,1301.9
  MidLayer1 w5: v1(996,907) 996,893 1054,835 1093,835 1094,836 1154,776 1264,776 1275,787 1336,787 1369,820 1681,820 1703,798 2041,798 2050,807 2050,829 2058,837 2096,837 2179,920 2545,920 2562,937 v1(2621,937)
  Bottom Layer w5: CN1.151@898.27,1882.17 924,1856.43 924,1796 975,1745 975,1711 992,1694 992,1457.5 968.5,1434 968.5,1407.5 950,1389 950,1158 964,1144 964,1116 975.5,1104.5 975.5,1071 990,1056.5 990,999 974,983 974,954 996,932 v1(996,907)
CAM4_D8: CN1.67 U12.14 | length 3339.1
  Top Layer w5: v1(2618,910) 2575.75,952.25 2575.75,992.25 2569.5,998.5 2569.5,1018 2564,1023.5 2564,1040 2545,1059 2545,1193 2553,1201 2553,1236 2552.5,1236.5 2572,1256 2572,1275 2618.58,1321.58 U12.14@2636.14,1321.58
  MidLayer1 w5: v1(786,874) 788,874 819,905 911,905 935,881 993,881 1050,824 1087,824 1145,766 1330,766 1374,810 1675,810 1697,788 2067,788 2103,824 2103,829 2184,910 v1(2618,910)
  Bottom Layer w5: CN1.67@698.27,1682.17 698.27,1667.73 720.5,1645.5 720.5,1629.5 733,1617 733,1285 751,1267 751,1092 737,1078 737,1047 763,1021 763,943 775,931 775,920 767,912 767,888 781,874 v1(786,874)
CAM4_D9: CN1.66 U12.13 | length 2915.8
  Top Layer w5: v1(2539,1033) 2539,1031 2540,1030 2540,1038 2535,1038 2535,1198 2541,1204 2541,1240 2560,1259 2560,1278 2623.27,1341.27 U12.13@2636.14,1341.27
  MidLayer1 w5: v1@733,1213 v1(733,1212) ; v1@737,1216 v1(733,1212) ; v1(2539,1033) 2539,1008 2501,970 2153,970 2103,920 2022,920 2014,912 2014,889 2003,878 1774,878 1744,848 1728,848 1706,870 1186,870 1121,935 1121,936 1073,984 1048,984 1012,1020 1012,1094 998,1108 959,1108 922,1145 838,1145 781.5,1201.5 743.5,1201.5 v1(733,1212)
  Bottom Layer w5: CN1.66@698.27,1632.17 722,1608.43 722,1279 733,1268 v1(733,1212)
CAM4_D10: CN4.17 U12.12 | length 3941.7
  Top Layer w5: v1(2514,1031) 2517,1034 2517,1055 2525,1063 2525,1239 2547,1261 2547,1280 2633.86,1366.86 U12.12@2661.73,1366.86
  MidLayer1 w5: v1(151,1336) 211,1336 230,1317 272,1317 277,1322 323,1322 337,1308 337,1278 371,1244 417,1244 436,1263 716,1263 763,1216 796,1216 808,1204 833,1204 845,1192 845,1184 873,1156 926,1156 964,1118 1003,1118 1022,1099 1022,1025 1053,994 1078,994 1191,881 1191,880 1333,880 1360,907 1385,907 1411,881 1488,881 1499,892 1951,892 1988,929 2005,929 2072,996 2121,996 2137,980 2489,980 2514,1005 v1@2514,1030 ; v1@2513,1030 v1@2514,1030 ; v1@2514,1030 v1(2514,1031) 2515,1030 v1@2514,1030
  Bottom Layer w5: v1(151,1336) 151,1391 139,1403 139,2029 CN4.17@193,2083
CAM4_D11: CN4.18 U12.11 | length 3969.4
  Top Layer w5: v1(2487,1029) 2499.5,1041.5 2499.5,1042.5 ; 2494,1037 2499.5,1042.5 ; U12.11@2681.42,1366.86 2681.42,1384.58 2678,1388 2642,1388 2637,1383 2635,1383 2537,1285 2537,1266 2515,1244 2515,1068 2503,1056 2503,1046 2499.5,1042.5
  MidLayer1 w5: v1(243,1335) 243,1334 334,1334 345,1323 448,1323 479,1292 501,1292 512,1303 710,1303 778,1235 797,1235 816,1216 836,1216 852,1200 897,1200 969,1128 1008,1128 1032,1104 1032,1030 1058,1004 1083,1004 1197,890 1328,890 1380,942 1436,942 1475,903 1947,903 1984,940 2001,940 2067,1006 2130,1006 2146,990 2477,990 2487,1000 v1(2487,1029) v1@2487,1030
  Bottom Layer w5: CN4.18@193,2183 243,2133 243,1633
  Bottom Layer w6: v1(243,1335) 243,1352 252,1361 252,1624 243,1633
CAM4_HS: CN1.158 U12.10 | length 3525.7
  Top Layer w5: v1(2485,1055) 2485,1063 2505,1083 2505,1249 2521,1265 2521,1284 2635,1398 2683,1398 2694,1387 2694,1373.96 U12.10@2701.1,1366.86
  MidLayer1 w5: v1(789,1295) 789,1293 818,1264 824,1264 848,1240 848,1224 860,1212 900,1212 974,1138 1013,1138 1067.5,1083.5 1085.5,1083.5 1159,1010 1336,1010 1380,1054 1520,1054 1606,968 1913,968 1943,998 1948,998 1948,999 1989,1040 2016,1040 2027,1029 2122,1029 2151,1000 2460,1000 2469,1009 2469,1039 2482,1052 2483,1052 2483,1053 v1(2485,1055)
  Bottom Layer w5: v1(789,1295) 789,1318 772,1335 772,1352 788,1368 788,1476 776,1488 776,1562 787,1573 787,1693 801,1707 801,1746 787,1760 787,1883 783,1887 783,2052 764,2071 764,2086 795,2117 795,2177 829,2211 881,2211 898.27,2228.27 CN1.158@898.27,2232.17
CAM4_PCLK: CN1.60 R106.1 | length 2685.1
  Top Layer w5: v1(2477,1112) 2477,1123 2485,1131 2485,1259 2501,1275 2501,1294 2642,1435 2678,1435 2677,1434 2673,1434 R106.1@2671,1432
  MidLayer1 w5: v1(676,1333) 724,1333 725,1334 746,1334 812,1400 889,1400 916,1373 916,1241 989,1168 1028,1168 1081,1115 1099,1115 1134,1080 1135,1080 1175,1040 1321,1040 1368,1087 1532,1087 1621,998 1898,998 1931,1031 1935,1031 1974,1070 2031,1070 2042,1059 2137,1059 2165,1031 2423,1031 2433,1041 2433,1066 2437,1070 2437,1088 2460,1111 2476,1111 2478,1109 v1@2480,1109 ; v1(2477,1112) v1@2480,1109 ; v1@2483,1109 v1@2480,1109
  Bottom Layer w5: v1(676,1333) 697.43,1333 CN1.60@698.27,1332.17
CAM4_VS: CN2.16 CN4.16 U12.9 | length 3905.3
  Top Layer w5: v1(2467,1075) 2467,1072 2479,1072 2495,1088 2495,1254 2511,1270 2511,1289 2630,1408 2688,1408 2720.79,1375.21 U12.9@2720.79,1366.86
  MidLayer1 w5: CN2.16@193,1384 219,1384 CN2.16@220,1383 ; v1(2467,1075) 2467,1074 2468,1075 2468,1060 2457,1049 2457,1024 2443,1010 2156,1010 2127,1039 2032,1039 2021,1050 1984,1050 1944,1010 1940,1010 1908,978 1611,978 1522.5,1066.5 1522,1066 1377,1066 1331,1020 1164,1020 1090,1094 1072,1094 1018,1148 979,1148 895,1232 895,1250 888,1257 872,1257 849,1280 849,1291 833,1307 811,1307 799,1319 738,1319 734,1315 509,1315 499,1305 481,1305 450,1336 347,1336 339,1344 274,1344 267,1351 252,1351 240,1363 ; CN2.16@220,1383 240,1363 ; CN2.16@220,1383 193,1383 213,1363 240,1363
  Bottom Layer w5: CN4.16@193,1983 152,1942 152,1425 CN2.16@193,1384 ; CN2.16@193,1384 193,1383 211,1365 212,1365 CN2.16@193,1384
CAM5_D0: CN2.5 U13.24 | length 926.1
  Top Layer w5: CN2.5@393,1483 395,1485 v1(463,1485) ; v1(480,1669) 480,1678 500,1698 656,1698 659,1701 933,1701 964,1732 992,1732 1025,1765 1025,1791 1035.26,1801.26 U13.24@1056.14,1801.26
  Bottom Layer w5: v1(463,1485) 455,1493 455,1543.5 482.5,1571 482.5,1593.5 475,1601 475,1664 v1(480,1669)
CAM5_D0_CAM5_VS: CN1.145 CN2.11 | length 669.1
  Top Layer w5: CN2.11@293,1483 CN2.11@293,1484 293,1500 318,1525 437,1525 456.5,1544.5 566,1544.5 581.5,1529 602,1529 635,1562 784,1562 796,1574 869,1574 v1(876,1581)
  Bottom Layer w5: v1(876,1581) 897.1,1581 CN1.145@898.27,1582.17
CAM5_D1: CN3.1 U13.23 | length 2099.4
  Top Layer w5: CN3.1@393,483 394,484 v1(536,484) ; v1(508,1716) 512,1720 550,1720 559,1711 928,1711 959,1742 987,1742 1009,1764 1009,1790 1039.94,1820.94 U13.23@1056.14,1820.94
  Bottom Layer w5: v1(508,1716) 508,1702 498,1692 498,1657 485,1644 485,1614 498,1601 498,1567 468,1537 468,1507 481,1494 481,1476 454,1449 454,1180 469,1165 469,963 486,946 486,896 502,880 504,880 504,867 530,841 530,793 515,778 515,698 532,681 532,648 522,638 522,581 510,569 510,510 v1(536,484)
CAM5_D1_CAM1_VS: CN1.82 CN3.7 | length 650.2
  MidLayer1 w5: v1(826,433) 821,428 761,428 759,426 703,426 690.5,413.5 670.5,413.5 670,413 642,441 588,441 583,436 530,436 526,440 335,440 329.5,445.5 ; 329.5,445.5 329.5,446.5 CN3.7@293,483 293,482 329.5,445.5
  Bottom Layer w5: v1(826,433) 847.43,433 CN1.82@848.27,432.17
CAM5_D2: CN3.2 U13.22 | length 1975.2
  Top Layer w5: CN3.2@393,583 407,597 v1(503,597) ; v1(469,1718) 486.5,1735.5 486.5,1756.5 494,1764 521,1764 533,1752 982,1752 999,1769 999,1795 1044.63,1840.63 U13.22@1056.14,1840.63
  Bottom Layer w5: v1(469,1718) 469,1705 444,1680 444,1175 459,1160 459,958 476,941 476,891 493,874 493,863 520,836 520,802 505,787 505,693 522,676 522,653 503,634 v1(503,597)
CAM5_D2_CAM1_D10: CN1.83 CN3.8 | length 597.2
  Top Layer w5: CN3.8@293,583 301,575 326,575 361,540 440,540 446,534 556,534 577,513 790,513 821,482 v1(826,482)
  Bottom Layer w5: v1(826,482) 826.17,482.17 CN1.83@848.27,482.17
CAM5_D3: CN3.3 U13.21 | length 1938.3
  Top Layer w5: CN3.3@393,683 411,665 503,665 v1(503,664) ; v1(466,1750) 466,1763 481,1778 526,1778 542,1762 977,1762 989,1774 989,1801 1008,1820 1009,1820 1025,1836 1025,1848 1037.32,1860.32 U13.21@1056.14,1860.31
  Bottom Layer w5: v1(466,1750) 434,1718 434,1170 449,1155 449,953 466,936 466,886 483,869 483,858 510,831 510,811 495,796 495,672 v1(503,664)
CAM5_D3_CAM1_D11: CN1.92 CN3.9 | length 856.3
  Top Layer w5: v1(504,914) 716,914 745,943 780,943 788,935 v1(826,935) ; v1(534,715) 534,716 527,723 334,723 CN3.9@294,683 ; CN3.9@294,683 CN3.9@293,683 293,682 CN3.9@294,683
  Bottom Layer w5: v1(504,914) 504,895 514,885 514,884 515,883 515,871 540,846 540,788 525,773 525,715 528,712 531,712 v1(534,715) ; v1(826,935) 828.83,932.17 CN1.92@848.27,932.17
CAM5_D4: CN3.4 U13.19 | length 1927.7
  Top Layer w5: CN3.4@393,783 524,783 v1(544,763) ; v1(472,1344) 475,1344 484,1353 495,1353 502,1360 688,1360 697,1369 714,1369 740,1395 v1(750.5,1395) ; v1(1033,1897) 1035.68,1899.68 U13.19@1056.14,1899.68
  MidLayer1 w5: v1(760,1899) 760,1901 890,1901 915,1876 971,1876 987,1892 1016,1892 1021,1897 v1(1033,1897)
  Bottom Layer w5: v1(472,1344) v1@473,1344 ; v1@476,1347 v1@473,1344 ; v1(544,763) 544,773 550,779 550,851 525,876 525,889 523,891 523,929 479,973 479,1170 470,1179 470,1341 v1@473,1344 ; v1(750.5,1395) 750.5,1395.5 746,1400 746,1578 757,1589 757,1745 753,1749 753,1758 746,1765 746,1804 738,1812 738,1877 v1(760,1899)
CAM5_D4_CAM2_VS: CN1.93 CN3.10 | length 867.5
  Top Layer w5: CN3.10@293,783 293,782 332,743 566,743 586,763 719,763 726,770 726,803 723,806 v1(723,808) ; v1(720,958) 740,958 767,985 v1(826,985)
  Bottom Layer w5: v1(720,958) 678,958 675,955 675,916 683,908 704,908 724,888 724,809 v1(723,808) ; v1(826,985) 845.43,985 CN1.93@848.27,982.17
CAM5_D5: CN3.5 U13.18 | length 1993.6
  Top Layer w5: CN3.5@393,883 394,882 507,882 512,887 541,887 v1(544,884) ; v1(489,1323) 584,1323 593,1314 706,1314 723,1297 v1(752,1297) v1@752,1298 ; v1@546,882 v1(544,884) ; v1@548,884 v1(544,884) ; v1(1033,1923) 1036.63,1919.37 U13.18@1056.14,1919.37
  MidLayer1 w5: v1(762,1872) 719,1872 708,1883 708,1917 715,1924 766,1924 779,1911 895,1911 920,1886 966,1886 982,1902 1011,1902 1032,1923 v1(1033,1923)
  Bottom Layer w5: v1(489,1323) 492,1323 480,1311 480,1184 489,1175 489,979 506,962 506,961 533,934 533,899 544,888 v1(544,884) ; v1(752,1297) 752,1362 768,1378 768,1466 756,1478 756,1572 767,1583 767,1750 763,1754 763,1765 756,1772 756,1809 748,1817 748,1858 v1(762,1872) ; v1(1033,1923) v1@1035,1921
CAM5_D5_CAM2_D10: CN1.98 CN3.11 | length 893.4
  Top Layer w5: v1(343,1230) 409,1230 426,1213 702,1213 727,1238 822,1238 v1(826,1234)
  Bottom Layer w5: CN3.11@293,883 342,932 343,932 v1(343,1230)
  Bottom Layer w17.72: v1(826,1234) 846.43,1234 CN1.98@848.27,1232.17
CAM5_D6: CN3.6 U13.16 | length 1792.7
  Top Layer w5: CN3.6@393,983 408,968 v1(527,968) ; v1(533,1949) 549,1949 563,1963 845,1963 850,1968 850,1990 860,2000 892,2000 905,2013 955,2013 968,2000 1016,2000 1024,1992 1024,1987 1032,1979 1032,1975 1048.26,1958.74 U13.16@1056.14,1958.74
  Bottom Layer w5: v1(527,968) 528,969 528,993 520,1001 520,1063 535,1078 535,1133 545,1143 545,1174 538,1181 538,1295 522,1311 522,1334 488,1368 488,1453 503,1468 503,1542 521,1560 521,1602 550,1631 550,1766 562,1778 562,1826 547,1841 547,1875 532,1890 533,1891 v1(533,1949)
CAM5_D6_CAM2_D11: CN1.99 CN3.12 | length 890.4
  Top Layer w5: CN3.12@293,982 CN3.12@293,983 333,1023 417,1023 453.5,986.5 454,987 v1(507,987) ; v1(499,1231) 503,1227 700,1227 724,1251 747,1251 772,1276 797,1276 804,1283 v1(826,1283)
  MidLayer1 w5: v1(499,1231) 499,1227 v1@502,1224
  Bottom Layer w5: v1(499,1231) 499,1223 490,1214 490,1189 499,1180 499,995 v1(507,987) v1@513,987
  Bottom Layer w17.72: v1(826,1283) 847.43,1283 CN1.99@848.27,1282.17
CAM5_D7: CN1.113 U13.15 | length 378
  Top Layer w5: v1(826,1981) 823,1978 797,1978 790,1985 790,1999 801,2010 887,2010 900,2023 960,2023 973,2010 1021,2010 1034.5,1996.5 1034.5,1991.5 1047.57,1978.43 U13.15@1056.14,1978.43 U13.15@1053.57,1981
  Bottom Layer w5: v1(826,1981) 847.1,1981 CN1.113@848.27,1982.17
CAM5_D8: CN1.114 U13.14 | length 369.7
  Top Layer w5: v1(826,2030) 824,2028 793,2028 787,2034 787,2043 796,2052 895,2052 910,2037 961,2037 978,2020 1026,2020 1047.89,1998.11 U13.14@1056.14,1998.11
  Bottom Layer w5: v1(826,2030) 846.1,2030 CN1.114@848.27,2032.17
CAM5_D9: CN1.116 U13.13 | length 319.1
  Top Layer w5: v1(825,2134) 848,2111 848,2084 869,2063 899,2063 915,2047 968,2047 985,2030 1043.94,2030 U13.13@1056.14,2017.8
  Bottom Layer w8: v1(825,2134) 846.43,2134 CN1.116@848.27,2132.17
CAM5_HS: CN1.26 U13.10 | length 931.4
  Top Layer w5: v1(1052,2077) 1061,2077 1074,2064 1117,2064 1121.1,2059.9 U13.10@1121.1,2043.39
  MidLayer1 w5: v1(596,1934) 612,1934 630,1952 648,1952 696,2000 888,2000 895,2007 982,2007 v1(1052,2077)
  Bottom Layer w5: v1(596,1934) 596,1912 616,1892 616,1863 627.5,1851.5 627.5,1652.93 CN1.26@648.27,1632.17
CAM5_PCLK: CN1.23 R130.1 | length 1172.6
  Top Layer w5: v1(1082,2112) 1105,2112 R130.1@1115,2102
  MidLayer1 w5: v1(570,1994) 580,2004 651,2004 699,2052 912,2052 972,2112 v1(1082,2112)
  Bottom Layer w5: v1(570,1994) 570,2004 577,1997 577,1916 606,1887 606,1854 617,1843 617,1605 607,1595 607,1578 625,1560 625,1502 644.83,1482.17 CN1.23@648.27,1482.17
CAM5_VS: CN2.17 U13.9 | length 1563.6
  Top Layer w5: v1(342,1440) 251,1440 250,1441 236,1441 CN2.17@194,1483 ; v1(1086,2083) 1096,2083 1101,2078 1121,2078 1140.79,2058.21 U13.9@1140.79,2043.39 ; CN2.17@194,1483 CN2.17@193,1484 193,1483 CN2.17@194,1483
  MidLayer1 w5: v1(449,1968) 450,1967 557,1967 561,1963 643,1963 691,2011 884,2011 890,2017 977,2017 1021,2061 1021,2076 1040,2095 1066,2095 1071,2090 1079,2090 v1(1086,2083)
  Bottom Layer w5: v1(342,1440) 350,1448 350,1621 352,1623 352,1689 349,1692 349,1725 353,1729 408,1729 433,1754 433,1829 442,1838 442,1961 v1(449,1968)
CAM6_D0: CN2.6 U14.24 | length 2779.2
  Top Layer w5: CN2.6@393,1583 397,1579 v1(463,1579) ; v1(2635,1767) 2635.14,1767.14 U14.24@2635.14,1782.26
  MidLayer1 w5: v1(489,1859) 534,1859 577,1816 628,1816 643,1801 1080,1801 1152,1729 1217,1729 1227,1739 1338,1739 1372,1773 1545,1773 1618,1700 1702,1700 1712,1710 1939,1710 1951,1722 1982,1722 1993,1733 1993,1765 2010,1782 2069,1782 2092,1759 2128.5,1759 2153,1734.5 2414.5,1734.5 2425,1745 2425,1748 2441,1764 2441,1775 2465,1799 2495,1799 2535,1759 2627,1759 v1(2635,1767) 2635,1768 2633,1768 v1@2632,1769
  Bottom Layer w5: v1(463,1579) 454,1588 454,1671 489,1706 489,1776 494,1781 494,1811 506,1823 506,1842 v1(489,1859)
CAM6_D0_CAM6_VS: CN1.146 CN2.12 | length 700.9
  Top Layer w5: v1@512,1630 511,1629 v1(505,1629) 506,1628 704,1628 718,1614 842,1614 859,1631 v1(876,1631)
  MidLayer1 w5: CN2.12@293,1583 310,1583 350,1543 429,1543 440,1554 440,1592 477,1629 v1(505,1629)
  Bottom Layer w5: v1(876,1631) 897.1,1631 CN1.146@898.27,1632.17
CAM6_D1: CN4.1 U14.23 | length 2741.4
  Top Layer w5: U14.23@2635.14,1801.94 2621.94,1801.94 2615,1795 2615,1762 2631,1746 2639,1746 2657,1728 v1(2657,1721)
  MidLayer1 w5: v1(488,1833) 488,1829 489,1828 545,1828 571.5,1801.5 621.5,1801.5 662,1761 944,1761 971,1788 1077,1788 1146,1719 1222,1719 1232,1729 1344,1729 1377,1762 1541,1762 1613,1690 1707,1690 1717,1700 1944,1700 1956,1712 1987,1712 2003,1728 2003,1760 2015,1772 2064,1772 2087,1749 2124,1749 2149,1724 2422,1724 2436,1738 2436,1744 2457,1765 2457,1776 2469,1788 2486,1788 2528,1746 2645,1746 2657,1734 v1(2657,1721)
  Bottom Layer w5: CN4.1@393,1683 393,1692 445,1744 445,1763 484,1802 484,1829 v1(488,1833)
CAM6_D1_CAM3_VS: CN1.54 CN4.7 | length 1146.6
  MidLayer1 w5: CN4.7@293,1683 251,1641 251,1556 272.5,1534.5 335,1534.5 344,1525.5 431.5,1525.5 436,1521 522,1521 v1(522,1520) ; v1(539,1045) 533,1039 533,1025 534,1025 560,999 580,999 596.5,1015.5 634.5,1015.5 652,1033 v1(676,1033)
  Bottom Layer w5: v1(522,1520) 513,1511 513,1369 532,1350 532,1316 548,1300 548,1186 555,1179 555,1135 545,1125 545,1051 v1(539,1045) ; v1(676,1033) 697.43,1033 CN1.54@698.27,1032.17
